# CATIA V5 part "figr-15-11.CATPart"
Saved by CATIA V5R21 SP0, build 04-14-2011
Part number: Part1
Bounding box of the stored display mesh (mm): x -50 to 50, y -32.5 to 33.5, z -52 to 1
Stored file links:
  D:\CATIA V5R21 E-RESOURCES\CATIA-V5R21\catia-v5r21-prt\c15-catia-v5r20-prt\c15-catia-v5r21-figr-15-11.CATPart
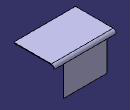
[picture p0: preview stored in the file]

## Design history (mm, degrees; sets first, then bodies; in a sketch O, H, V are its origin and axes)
SheetMetalParameters1: Thickness 1, BendRadius 4, KFactor 0.475772 {= log(min(100,max(20*SheetMetalParameters1.BendRadius,SheetMetalParameters1.Thickness)/SheetMetalParameters1.Thickness))/log(100)/2}, ReliefRadialLength 4, ReliefAxialLength 4, MinimumBendRadius 0
Body1 (main body)
  Sketch1 on xy-plane, origin (0, 0, 0), H (1, 0, 0), V (0, 1, 0)
    line L1 (-50, 32.5) -> (50, 32.5)
    line L2 (50, 32.5) -> (50, -32.5)
    line L3 (50, -32.5) -> (-50, -32.5)
    line L4 (-50, -32.5) -> (-50, 32.5)
    length L1 = 100
    length L2 = 65
    horizontal: L1 H, L3 H
    vertical: L2 V, L4 V
    symmetry: L4 L2 V, L1 L3 H
  Wall1: Thickness 1, Profile Sketch1
  d_NewWallOnEdge1: NewWallOnEdge_Edge edge [face of Wall1 | face of Wall1], NewWallOnEdge_Length 53, NewWallOnEdge_HeightLimitOffset 0, NewWallOnEdge_WidthOffset1 -15, NewWallOnEdge_WidthOffset2 -15, NewWallOnEdge_Angle 90, NewWallOnEdge_BendRadiusValue 4 {= SheetMetalParameters1.BendRadius}, NewWallOnEdge_BendTable SheetMetalParameters1, KFacteur 0.475772 {= log(min(100,max(20*d_NewWallOnEdge1.Radius,SheetMetalParameters1.Thickness)/SheetMetalParameters1.Thickness))/log(100)/2}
